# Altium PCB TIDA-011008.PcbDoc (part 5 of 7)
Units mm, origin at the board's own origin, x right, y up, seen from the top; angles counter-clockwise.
Board outline 252 x 205 mm, 4 copper layers (Top Layer, Inner Layer 1, Inner Layer 2, Bottom Layer), stack 1.926 mm thick; 517 components, 293 nets, 1426 pads, 1855 vias.
Unrouted connection lines stored in the file: 4.
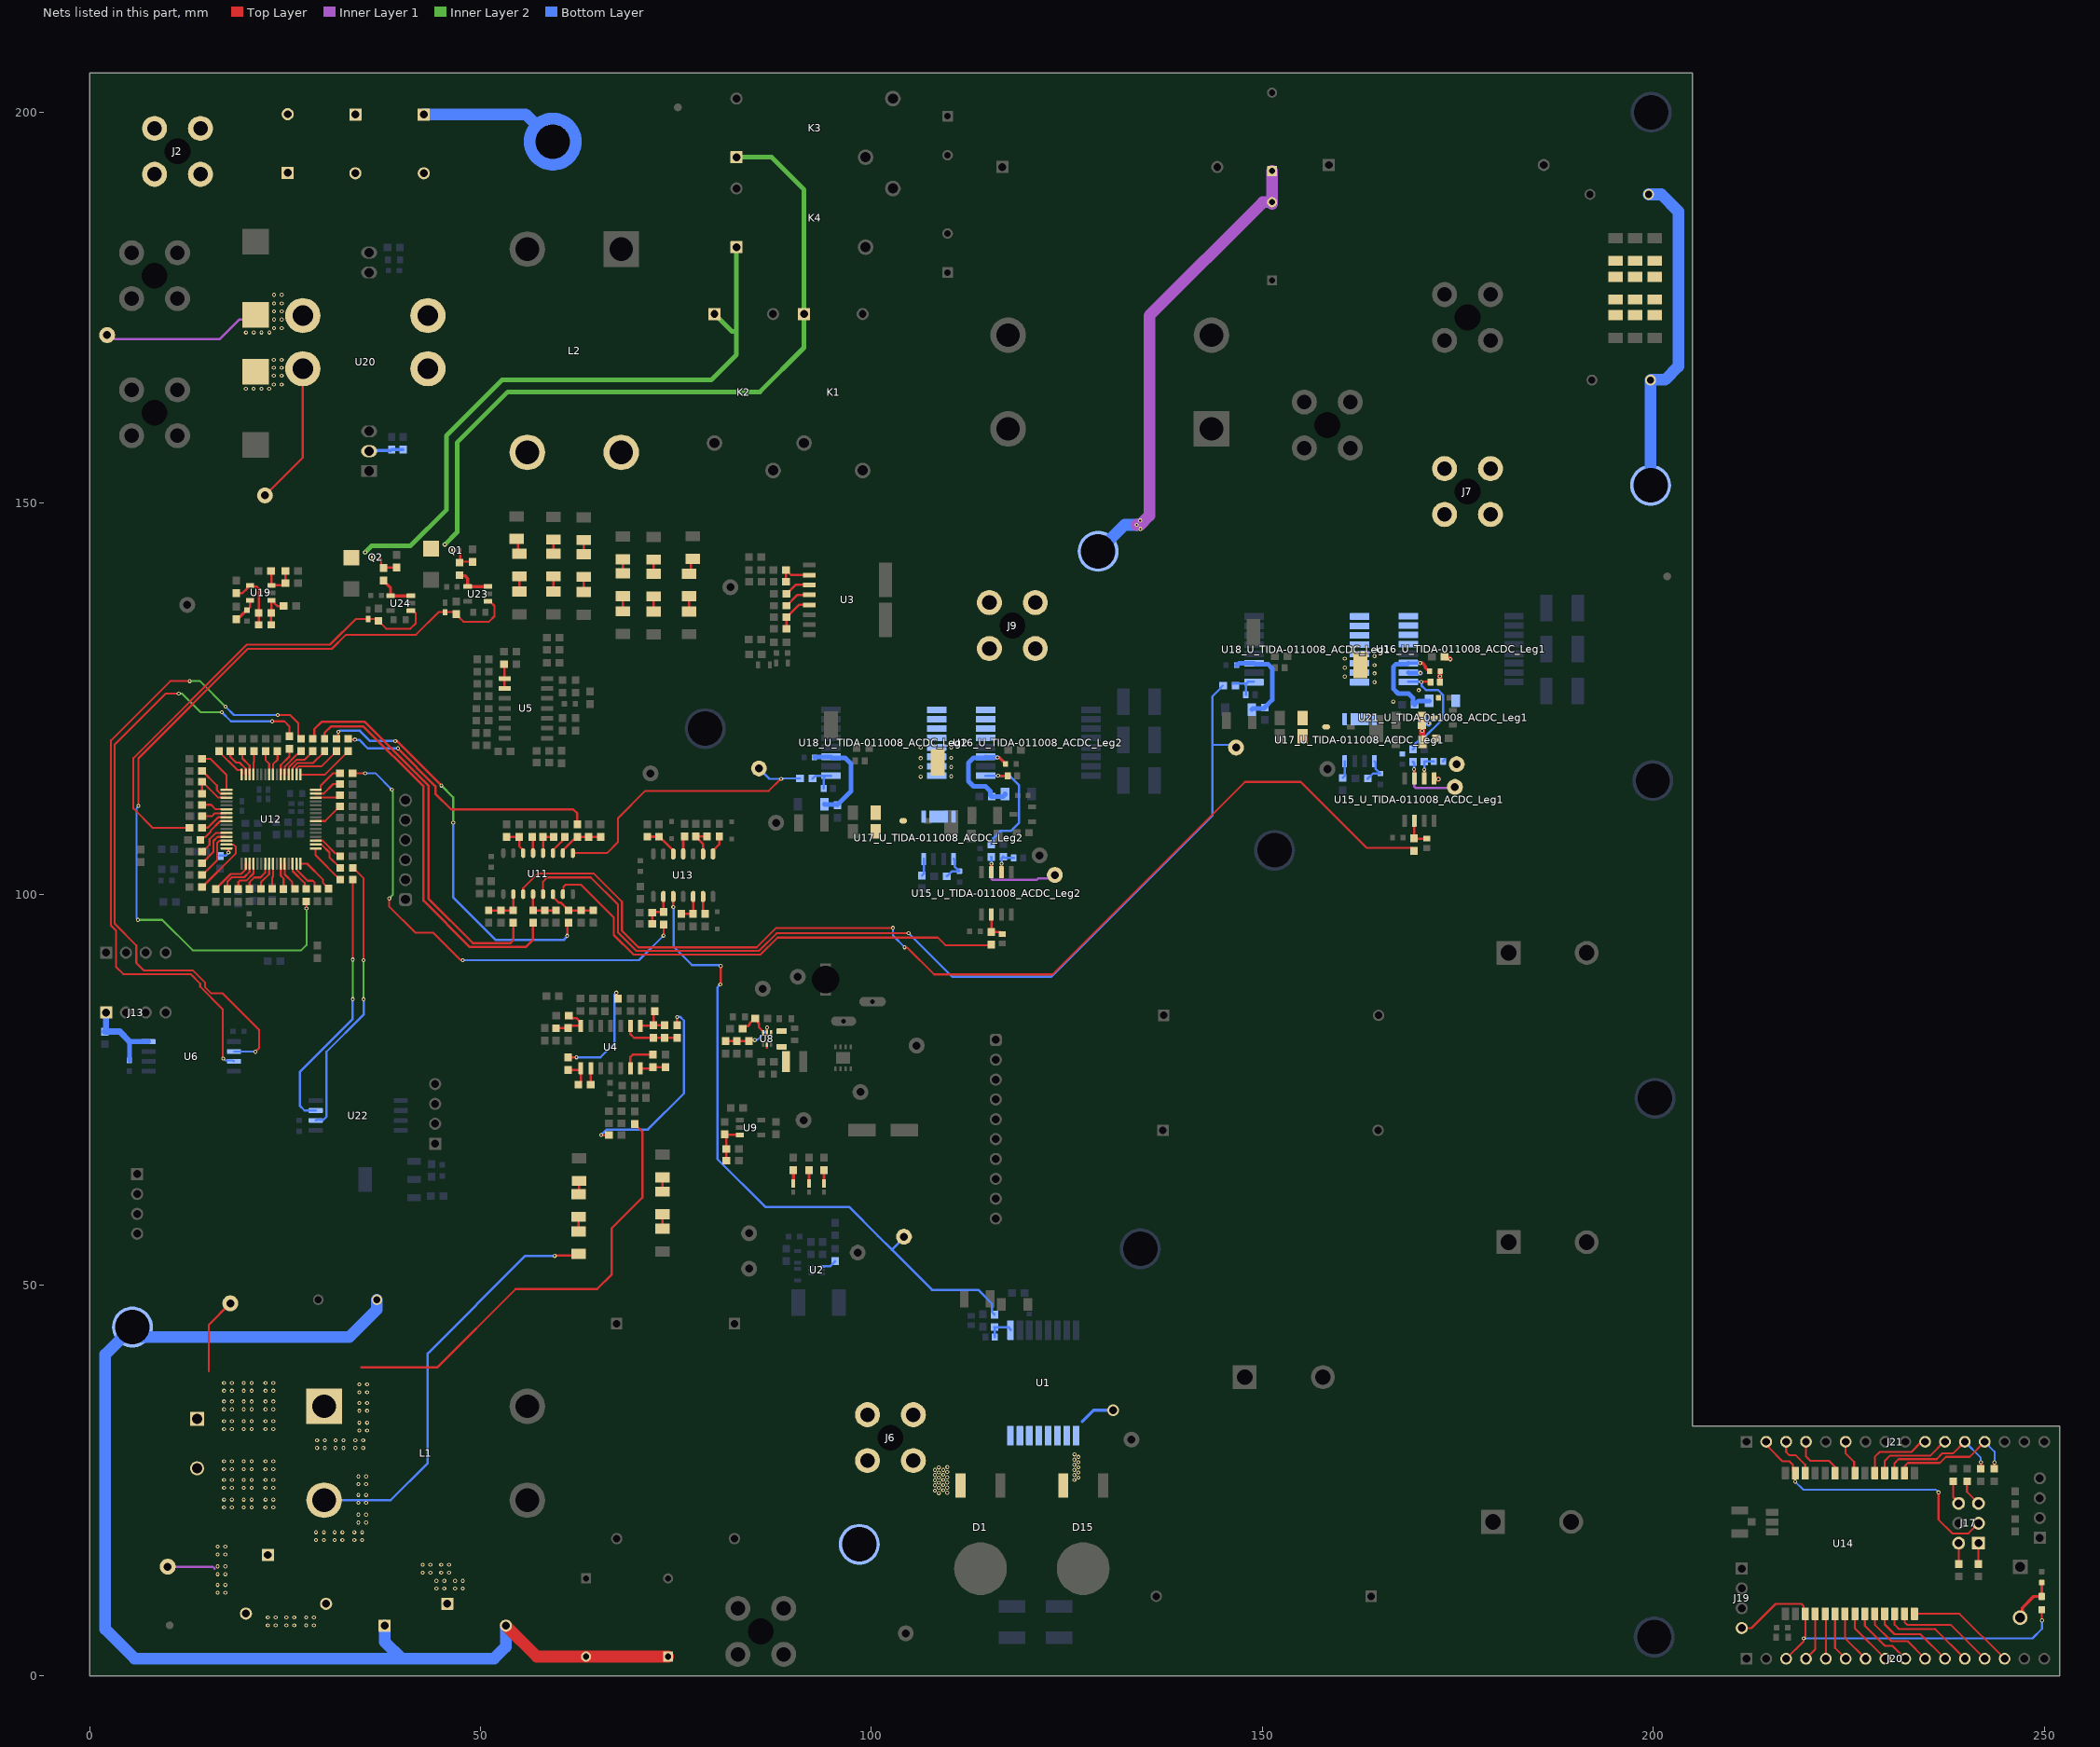
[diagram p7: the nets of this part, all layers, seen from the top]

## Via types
v1: diameter 0.508, hole 0.254, Top Layer to Bottom Layer, tented both sides, 1852 vias
v2: diameter 1.5/1.5/1.5/1.5 (per signal layer), hole 1, Top Layer to Bottom Layer, 2 vias
v3: diameter 0.508, hole 0.254, Top Layer to Bottom Layer, 1 vias

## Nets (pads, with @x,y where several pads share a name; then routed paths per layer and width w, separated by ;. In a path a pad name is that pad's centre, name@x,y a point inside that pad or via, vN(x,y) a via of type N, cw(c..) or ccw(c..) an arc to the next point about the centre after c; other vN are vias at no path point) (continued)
NetC63_2: C63.2 R86.1 R90.1 U4.14 | length 5.7
  Top Layer w0.3: R90.1@59.678,82.861 59.685,82.867 C63.2@61.204,82.867 61.505,83.168 62.844,83.168 62.844,83.593 62.279,84.158 61.604,84.158 R86.1@61.279,84.483
NetC64_1: C64.1 R89.1 R91.2 U4.9 | length 7.2
  Top Layer w0.3: U4.9@69.194,83.168 69.194,82.082 69.645,81.631 C64.1@72.146,81.631 R89.1@75.154,81.631
NetC64_2: C64.2 R87.1 R91.1 U4.8 | length 5
  Top Layer w0.3: U4.8@70.464,83.168 72.083,83.168 C64.2@72.146,83.231 ; R87.1@72.318,85.04 72.146,84.868 C64.2@72.146,83.231 ; R91.1@73.574,83.231 C64.2@72.146,83.231
NetC66_2: C66.2 J13.1 L6.2 U6.8 | length 10.5
  Bottom Layer w0.6: C66.2@5.093,78.76 5.093,81.112 ; 5.136,81.155 U6.8@7.56,81.155
  Bottom Layer w0.8: L6.2@1.961,82.431 3.86,82.431 5.136,81.155 5.093,81.112 ; L6.2@2.11,82.904 J13.1@2.11,84.879
NetC70_1: C70.1 L5.1 U8.2 | length 0.7
  Top Layer w0.3: 86.658,80.404 U8.2@86.658,80.785 ; C70.1@88.233,80.484 C70.1@88.533,80.484
NetC70_2: C70.2 U8.4
NetC78_2: C78.2 R101.1 R104.2 U9.3 | length 5.3
  Top Layer w0.3: R101.1@81.259,69.272 R101.1@81.323,69.208 ; C78.2@81.458,65.908 R104.2@81.458,67.408 81.458,69.073 R101.1@81.323,69.208 ; U9.3@83.183,69.208 R101.1@81.323,69.208
NetC81_2: C81.2 R102.1 R106.2 U8.5 | length 6.9
  Top Layer w0.254: v1(86.655,82.941) 86.657,82.94 86.657,82.266 U8.5@86.658,82.265
  Top Layer w0.3: C81.2@81.383,81.215 81.386,81.219 R106.2@82.808,81.219 82.81,81.217 R102.1@84.358,81.217 84.489,81.349 v1(85.083,81.349)
  Bottom Layer w0.254: v1(85.083,81.349) 85.122,81.388 85.428,81.388 86.626,82.586 86.626,82.912 v1(86.655,82.941)
NetC82_1: C82.1 R115.2 U11.12 | length 3.4
  Top Layer w0.3: U11.12@58.003,105.26 R115.2@58.003,107.335 C82.1@59.368,107.335
NetC83_1: C83.1 R118.2 U11.14 | length 3.9
  Top Layer w0.3: C83.1@53.368,107.335 R118.2@54.963,107.335 54.963,106.135 55.463,105.635 U11.14@55.463,105.26
NetC85_1: C85.1 R108.2 R128.2 U11.2 | length 5.2
  Top Layer w0.3: R128.2@51.047,97.935 C85.1@52.643,97.935 54.193,97.935 U11.2@54.193,100.01
NetC86_1: C86.1 R109.2 R129.2 U11.4 | length 5
  Top Layer w0.3: U11.4@56.733,100.01 R109.2@56.733,97.935 R129.2@58.253,97.935 C86.1@59.682,97.935
NetC87_1: C87.1 R111.2 R130.2 U11.6 | length 6.2
  Top Layer w0.3: U11.6@59.273,100.01 59.273,99.66 59.985,98.948 60.28,98.948 61.268,97.96 R111.2@61.268,97.935 R130.2@62.868,97.935 C87.1@64.406,97.935
NetC88_1: C88.1 R113.2 R131.2 U11.10 | length 5.9
  Top Layer w0.3: U11.10@60.543,105.26 60.543,105.61 61.918,106.985 62.068,106.985 62.393,107.31 R113.2@62.393,107.335 R131.2@63.831,107.335 C88.1@65.368,107.335
NetC90_1: C90.1 R142.2 R144.2 U13.2 | length 4.9
  Top Layer w0.3: C90.1@71.982,96.206 R144.2@71.982,97.635 72.079,97.731 R142.2@73.432,97.731 73.392,97.771 U13.2@73.392,99.706
NetC91_1: C91.1 R150.2 U13.5 | length 3.7
  Top Layer w0.3: C91.1@75.669,97.481 R150.2@77.169,97.481 77.202,97.515 U13.5@77.202,99.706
NetC96_1: C96.1 R153.2 U13.12 | length 4.5
  Top Layer w0.3: C96.1@71.319,107.355 R153.2@72.83,107.355 72.83,107.33 73.155,107.005 73.239,107.005 74.662,105.581 U13.12@74.662,105.156
NetC101_1: C101.1 R159.2 U13.9 | length 4.1
  Top Layer w0.3: U13.9@78.472,105.156 78.472,106.403 77.519,107.356 C101.1@77.519,107.381 R159.2@78.979,107.381
NetC102_1: C102.1 R158.1 U12.3 | length 5.5
  Top Layer w0.254: R158.1@14.39,112.865 C102.1@14.39,114.365 14.738,114.017 14.824,114.017 16.489,112.352 U12.3@17.515,112.352
NetC107_2: C107.2 R164.1 SW1.2 | length 6.2
  Top Layer w0.4: SW1.2@246.94,7.47 247.225,7.755 247.225,8.745 248.67,10.19 R164.1@249.69,10.19 C107.2@249.69,11.96
NetC112_U_TIDA-011008_ACDC_Leg1_1: C112_U_TIDA-011008_ACDC_Leg1.1 C113_U_TIDA-011008_ACDC_Leg1.2 R173_U_TIDA-011008_ACDC_Leg1.2 U16_U_TIDA-011008_ACDC_Leg1.11 | length 14.2
  Top Layer w0.4: v1(170.195,129.562) 170.214,129.542 170.484,129.542 170.87,129.157 170.87,128.964 171.167,128.667 171.269,128.667 171.394,128.542 C113_U_TIDA-011008_ACDC_Leg1.2@171.394,128.517
  Bottom Layer w0.4: U16_U_TIDA-011008_ACDC_Leg1.11@168.691,129.558 170.191,129.558 v1(170.195,129.562)
  Bottom Layer w0.6: U16_U_TIDA-011008_ACDC_Leg1.11@168.691,129.558 U16_U_TIDA-011008_ACDC_Leg1.11@168.687,129.554 168.562,129.429 167.094,129.429 166.755,129.089 166.755,126.279 167.377,125.657 168.721,125.657 169.278,125.1 169.278,124.424 169.453,124.249 R173_U_TIDA-011008_ACDC_Leg1.2@169.478,124.249 169.503,124.249 169.972,124.719 C112_U_TIDA-011008_ACDC_Leg1.1@171.35,124.719
NetC112_U_TIDA-011008_ACDC_Leg2_1: C112_U_TIDA-011008_ACDC_Leg2.1 C113_U_TIDA-011008_ACDC_Leg2.2 R173_U_TIDA-011008_ACDC_Leg2.2 U16_U_TIDA-011008_ACDC_Leg2.11 | length 13.8
  Top Layer w0.4: v1(116.137,117.489) 116.156,117.469 116.385,117.469 117.18,116.675 C113_U_TIDA-011008_ACDC_Leg2.2@117.18,116.65
  Bottom Layer w0.6: v1(116.137,117.489) 114.692,117.489 U16_U_TIDA-011008_ACDC_Leg2.11@114.605,117.576 114.48,117.451 113.08,117.451 112.422,116.793 112.422,114.447 113.072,113.797 114.591,113.797 115.199,113.189 115.199,112.667 115.374,112.492 R173_U_TIDA-011008_ACDC_Leg2.2@115.399,112.492 116.843,112.492 117.093,112.742 C112_U_TIDA-011008_ACDC_Leg2.1@117.093,112.827
NetC114_U_TIDA-011008_ACDC_Leg1_2: C114_U_TIDA-011008_ACDC_Leg1.2 R176_U_TIDA-011008_ACDC_Leg1.1 U15_U_TIDA-011008_ACDC_Leg1.6 | length 3.4
  Top Layer w0.3: U15_U_TIDA-011008_ACDC_Leg1.6@170.722,114.804 v1(170.722,115.921)
  Bottom Layer w0.3: v1(170.722,115.921) R176_U_TIDA-011008_ACDC_Leg1.1@170.722,116.95 170.764,116.992 C114_U_TIDA-011008_ACDC_Leg1.2@171.944,116.992
NetC114_U_TIDA-011008_ACDC_Leg2_2: C114_U_TIDA-011008_ACDC_Leg2.2 R176_U_TIDA-011008_ACDC_Leg2.1 U15_U_TIDA-011008_ACDC_Leg2.6 | length 3.5
  Top Layer w0.3: U15_U_TIDA-011008_ACDC_Leg2.6@116.627,102.808 116.627,103.876 v1(116.656,103.904)
  Inner Layer 1 w0.3: v1(116.656,103.904) v1@116.71,103.904
  Bottom Layer w0.3: v1(116.656,103.904) 116.656,104.591 R176_U_TIDA-011008_ACDC_Leg2.1@116.861,104.796 116.988,104.668 C114_U_TIDA-011008_ACDC_Leg2.2@118.204,104.668
NetC116_U_TIDA-011008_ACDC_Leg1_1: C116_U_TIDA-011008_ACDC_Leg1.1 R174_U_TIDA-011008_ACDC_Leg1.2 U15_U_TIDA-011008_ACDC_Leg1.2 | length 3.9
  Top Layer w0.3: U15_U_TIDA-011008_ACDC_Leg1.2@169.452,109.404 169.452,107.194 R174_U_TIDA-011008_ACDC_Leg1.2@169.412,107.154 169.459,107.107 C116_U_TIDA-011008_ACDC_Leg1.1@171.03,107.107
NetC116_U_TIDA-011008_ACDC_Leg2_1: C116_U_TIDA-011008_ACDC_Leg2.1 R174_U_TIDA-011008_ACDC_Leg2.2 U15_U_TIDA-011008_ACDC_Leg2.2 | length 3.9
  Top Layer w0.3: U15_U_TIDA-011008_ACDC_Leg2.2@115.357,97.408 115.357,95.198 R174_U_TIDA-011008_ACDC_Leg2.2@115.317,95.158 116.492,95.158 C116_U_TIDA-011008_ACDC_Leg2.1@116.742,94.908 C116_U_TIDA-011008_ACDC_Leg2.1@116.742,94.833
NetC118_U_TIDA-011008_ACDC_Leg1_1: C118_U_TIDA-011008_ACDC_Leg1.1 FB7_U_TIDA-011008_ACDC_Leg1.2 U17_U_TIDA-011008_ACDC_Leg1.1 | length 3.7
  Bottom Layer w0.3: C118_U_TIDA-011008_ACDC_Leg1.1@163.499,114.795 163.524,114.795 164.165,115.436 FB7_U_TIDA-011008_ACDC_Leg1.2@165.104,115.436 164.479,116.06 164.479,116.878 U17_U_TIDA-011008_ACDC_Leg1.1@164.354,117.004
NetC118_U_TIDA-011008_ACDC_Leg2_1: C118_U_TIDA-011008_ACDC_Leg2.1 FB7_U_TIDA-011008_ACDC_Leg2.2 U17_U_TIDA-011008_ACDC_Leg2.1 | length 3.7
  Bottom Layer w0.3: C118_U_TIDA-011008_ACDC_Leg2.1@109.655,102.299 109.68,102.299 110.321,102.94 FB7_U_TIDA-011008_ACDC_Leg2.2@111.26,102.94 110.636,103.565 110.636,104.382 U17_U_TIDA-011008_ACDC_Leg2.1@110.51,104.508
NetC124_U_TIDA-011008_ACDC_Leg1_1: C124_U_TIDA-011008_ACDC_Leg1.1 C125_U_TIDA-011008_ACDC_Leg1.2 R179_U_TIDA-011008_ACDC_Leg1.2 U18_U_TIDA-011008_ACDC_Leg1.11 | length 12.1
  Bottom Layer w0.6: C125_U_TIDA-011008_ACDC_Leg1.2@146.713,129.279 146.713,129.304 146.738,129.329 146.838,129.329 147.026,129.517 U18_U_TIDA-011008_ACDC_Leg1.11@148.938,129.517 ; C124_U_TIDA-011008_ACDC_Leg1.1@148.674,123.623 148.799,123.748 150.192,123.748 R179_U_TIDA-011008_ACDC_Leg1.2@150.317,123.873 150.317,123.898 151.262,124.843 151.262,128.882 150.716,129.429 149.062,129.429 U18_U_TIDA-011008_ACDC_Leg1.11@148.937,129.554
NetC124_U_TIDA-011008_ACDC_Leg2_1: C124_U_TIDA-011008_ACDC_Leg2.1 C125_U_TIDA-011008_ACDC_Leg2.2 R179_U_TIDA-011008_ACDC_Leg2.2 U18_U_TIDA-011008_ACDC_Leg2.11 | length 12.8
  Bottom Layer w0.6: C125_U_TIDA-011008_ACDC_Leg2.2@92.728,117.486 92.728,117.497 92.753,117.522 94.806,117.522 94.842,117.558 94.967,117.433 96.642,117.433 97.399,116.677 97.399,113.166 95.648,111.415 R179_U_TIDA-011008_ACDC_Leg2.2@95.648,111.39 95.59,111.448 94.049,111.448 C124_U_TIDA-011008_ACDC_Leg2.1@93.992,111.505
NetC128_2: C128.2 U12.16 | length 2.1
  Top Layer w0.3: U12.16@17.515,105.852 17.771,105.852 v1(17.771,105.327)
  Bottom Layer w0.3: C128.2@16.665,104.942 17.439,104.942 17.771,105.274 v1(17.771,105.327) v1@17.771,105.381
NetC130_1: C130.1 FB8.2 U19.5 | length 3.3
  Top Layer w0.3: FB8.2@20.132,136.323 20.525,136.716 U19.5@20.525,137.594
  Top Layer w0.4: C130.1@18.747,135.15 18.747,135.175 19.022,135.45 19.224,135.45 19.947,136.173 19.982,136.173 FB8.2@20.132,136.323
NetC131_1: C131.1 R196.1 R197.2 U19.3 | length 5.3
  Top Layer w0.3: R196.1@23.2,141.35 23.275,141.275 U19.3@23.275,139.494 24.753,139.494 R197.2@25.065,139.807 C131.1@25.065,141.307
NetC133_1: C133.1 R195.1 R198.1 U19.1 | length 5.1
  Top Layer w0.3: C133.1@23.235,134.448 R198.1@23.235,135.963 23.275,136.003 U19.1@23.275,137.594 23.475,137.594 23.625,137.444 23.625,137.244 24.015,136.855 R195.1@24.808,136.855
NetC133_2: C133.2 R194.1 R198.2 U19.4 | length 8.2
  Top Layer w0.3: R194.1@18.747,138.5 19.531,138.5 20.175,139.144 20.175,139.344 20.325,139.494 U19.4@20.525,139.494 20.675,139.344 21.36,139.344 21.635,139.069 R198.2@21.635,135.963 C133.2@21.635,134.448
NetC134_1: C134.1 R201.2 U20.2 | length 4.4
  Bottom Layer w0.4: U20.2@35.762,156.66 35.859,156.757 38.551,156.757 C134.1@38.648,156.854 38.649,156.855 R201.2@40.104,156.856 R201.2@40.104,156.856
NetD1_3: D1.3 D15.3 J6.1 U1.1 U1.2 U1.3 U1.4 U1.5 U1.6 U1.7 U1.8 | length 4.5
  Bottom Layer w0.4: 127,32.59 128.423,34.013 v2(130.938,34.013)
  other v1: 108.628,23.41 109.7,23.452 108.114,23.736 109.18,23.775 108.635,24.08 109.7,24.114 108.114,24.411 109.18,24.436 108.635,24.739 109.7,24.766 108.114,25.071 125.965,25.08 109.18,25.088 108.635,25.391 126.486,25.391 109.7,25.425 125.965,25.713 108.114,25.723 109.18,25.747 126.486,26.043 108.635,26.053 109.7,26.101 108.114,26.375 125.965,26.374 109.197,26.381 108.635,26.685 126.486,26.695 109.717,26.734 125.965,27.026 126.486,27.354 125.965,27.686 126.486,28.03 125.973,28.355
NetD6_1: D6.1 R98.1 | length 1.7
  Top Layer w0.4: D6.1@93.933,63.015 R98.1@93.933,64.695
NetD7_1: D7.1 R99.2 | length 1.7
  Top Layer w0.4: D7.1@92.033,63.015 R99.2@92.033,64.695
NetD8_1: D8.1 R100.2 | length 1.7
  Top Layer w0.4: D8.1@90.012,63.015 R100.2@90.012,64.695
NetD13_U_TIDA-011008_ACDC_Leg1_2: D13_U_TIDA-011008_ACDC_Leg1.2 R171_U_TIDA-011008_ACDC_Leg1.2 R172_U_TIDA-011008_ACDC_Leg1.2
NetD13_U_TIDA-011008_ACDC_Leg2_2: D13_U_TIDA-011008_ACDC_Leg2.2 R171_U_TIDA-011008_ACDC_Leg2.2 R172_U_TIDA-011008_ACDC_Leg2.2
NetF1_1: F1.1 TP11.1 U20.8 | length 20.2
  Inner Layer 1 w0.3: TP11.1@2.25,171.5 2.719,171.5 3.212,171.007 16.674,171.007 19.167,173.5 21.25,173.5
  other v1: 20.005,171.837 21,171.837 22,171.837 22.995,171.837 23.591,172.392 24.586,172.392 23.591,173.5 24.586,173.5 23.591,174.536 24.586,174.536 23.591,175.536 24.586,175.536 23.591,176.644 24.586,176.644
NetF2_1: F2.1 TP12.1 U20.9 | length 19.2
  Top Layer w0.3: TP12.1@22.435,151 27.282,155.847 U20.9@27.282,167.2
  Top Layer w1: U20.9@27.282,167.2 U20.9@28.229,167.2
  other v1: 19.986,164.634 20.981,164.634 21.981,164.634 22.977,164.634 23.572,165.189 24.567,165.189 23.572,166.297 24.567,166.297 23.572,167.333 24.567,167.333 23.572,168.333 24.567,168.333
NetJ17_1: J17.1 R162.1 | length 2.7
  Top Layer w0.254: R162.1@241.605,14.35 J17.1@241.605,17.01
NetJ17_2: J17.2 R163.1 | length 2.7
  Top Layer w0.254: J17.2@239.065,17.01 239.065,14.37 R163.1@239.085,14.35
NetJ17_5: J17.5 R165.2 | length 3.7
  Top Layer w0.254: R165.2@240.135,25.168 R165.2@240.135,24.918 240.135,23.56 J17.5@241.605,22.09
NetJ17_6: J17.6 R166.2 | length 3.1
  Top Layer w0.254: R166.2@238.36,24.918 238.36,22.88 239.065,22.175 J17.6@239.065,22.09
NetL2_3: L2.3 R13.1 R17.2 U20.6
NetL2_4: L2.4 R17.1 R24.2 U20.7
NetQ1_1: Q1.1@47.398,143.989 R27.2 R92.2 | length 2.9
  Top Layer w0.254: Q1.1@47.4,143.871 47.403,143.868 47.403,142.501 47.411,142.51 R92.2@48.964,142.51
NetQ2_1: Q2.1@37.114,143.095 R34.2 R93.2 | length 3.2
  Top Layer w0.254: Q2.1@37.116,142.977 37.169,142.977 37.32,142.826 R34.2@37.32,141.991
  Top Layer w0.3: R34.2@37.32,141.991 R34.2@37.607,141.704 37.675,141.772 R93.2@39.3,141.772
NetR8_1: R8.1 U2.1 | length 1.9
  Bottom Layer w0.3: U2.1@93.74,52.442 94.75,52.442 95.35,53.042 R8.1@95.35,53.067
NetR14_1: R14.1 R15.1 R16.1 R18.2 R19.2 R20.2
NetR18_1: R18.1 R19.1 R20.1 R21.2 R22.2 R23.2
NetR26_1: R26.1 U3.6 | length 3.5
  Top Layer w0.3: R26.1@89.121,136.89 89.146,136.89 90.531,138.276 U3.6@92.053,138.276
NetR27_1: R27.1 U23.3 U23.4 | length 4.9
  Top Layer w0.4: R27.1@47.302,140.801 47.366,140.737 47.993,140.737 48.365,140.366 U23.4@48.365,139.343 U23.3@50.965,139.343
NetR29_1: R29.1 R33.1 U3.4 | length 4.7
  Top Layer w0.3: R33.1@89.095,139.98 89.077,139.999 R29.1@89.077,141.446 89.102,141.446 89.732,140.816 U3.4@92.053,140.816
NetR30_1: R30.1 R32.1 U3.7 | length 5
  Top Layer w0.3: R30.1@89.121,133.959 R32.1@89.121,135.415 89.146,135.415 90.736,137.006 U3.7@92.053,137.006
NetR31_2: R31.2 U3.5 | length 3.4
  Top Layer w0.3: R31.2@89.127,138.39 89.152,138.39 90.308,139.546 U3.5@92.053,139.546
NetR34_1: R34.1 U24.3 U24.4 | length 4.9
  Top Layer w0.4: R34.1@37.607,140.104 37.607,140.079 38.501,139.185 U24.4@38.501,138.152 U24.3@41.101,138.152
NetR39_1: R39.1 R41.1 U4.1 | length 3.7
  Top Layer w0.3: R41.1@61.204,77.543 U4.1@62.706,77.543 ; R39.1@62.519,75.652 62.844,75.977 U4.1@62.844,77.718
NetR39_2: R39.2 U4.2 | length 2.1
  Top Layer w0.3: U4.2@64.114,77.718 64.114,75.657 R39.2@64.119,75.652
NetR40_1: R40.1 R42.1 U4.7 | length 3.3
  Top Layer w0.3: U4.7@70.464,77.718 71.914,77.718 R40.1@72.064,77.868 R42.1@73.654,77.868
NetR40_2: R40.2 U4.6 | length 4.5
  Top Layer w0.3: U4.6@69.194,77.718 69.194,79.19 69.472,79.468 R40.2@72.064,79.468
NetR43_2: R43.2 R44.1 | length 1.6
  Top Layer w0.3: R43.2@62.574,57.032 R44.1@62.574,58.589
NetR44_2: R44.2 R45.1 | length 1.4
  Top Layer w0.3: R44.2@62.574,61.789 62.597,61.812 62.597,63.159 R45.1@62.619,63.182
NetR46_2: R46.2 R47.1 | length 1.5
  Top Layer w0.3: R46.2@73.256,57.362 R47.1@73.256,58.912
NetR47_2: R47.2 R48.1 | length 1.5
  Top Layer w0.3: R47.2@73.256,62.112 R48.1@73.256,63.632
NetR49_1: R49.1 U5.8 U5.9 | length 3.1
  Top Layer w0.3: R49.1@52.993,129.397 53.101,129.289 53.101,127.574 U5.9@53.101,126.304
NetR58_2: R58.2 R59.1 | length 1.5
  Top Layer w0.3: R59.1@63.221,143.642 R58.2@63.221,145.15
NetR59_2: R59.2 R60.1 | length 1.6
  Top Layer w0.3: R60.1@63.221,138.802 R59.2@63.221,140.442
NetR61_2: R61.2 R62.1 | length 1.5
  Top Layer w0.3: R62.1@59.34,143.694 R61.2@59.34,145.203
NetR62_2: R62.2 R63.1 | length 1.6
  Top Layer w0.3: R63.1@59.34,138.854 R62.2@59.34,140.494
NetR64_2: R64.2 R65.1 | length 1.8
  Top Layer w0.3: R65.1@76.706,141.142 76.915,141.35 76.915,142.484 R64.2@77.153,142.722
NetR65_2: R65.2 R66.1 | length 1.6
  Top Layer w0.3: R66.1@76.706,136.302 R65.2@76.706,137.942
NetR70_2: R70.2 R71.1 | length 1.5
  Top Layer w0.3: R71.1@68.201,141.162 R70.2@68.201,142.671
NetR71_2: R71.2 R72.1 | length 1.6
  Top Layer w0.3: R72.1@68.201,136.323 R71.2@68.201,137.962
NetR73_2: R73.2 R74.1 | length 1.7
  Top Layer w0.3: R73.2@54.595,145.277 54.822,145.05 54.822,143.873 R74.1@54.995,143.7
NetR74_2: R74.2 R75.1 | length 1.6
  Top Layer w0.3: R75.1@54.995,138.86 R74.2@54.995,140.5
NetR76_2: R76.2 R77.1 | length 1.5
  Top Layer w0.3: R77.1@72.136,141.135 R76.2@72.136,142.643
NetR77_2: R77.2 R78.1 | length 1.6
  Top Layer w0.3: R78.1@72.136,136.295 R77.2@72.136,137.935
NetR103_1: R103.1 R105.2 U8.6 | length 4.5
  Top Layer w0.3: R105.2@83.533,82.808 83.858,83.133 84.225,83.133 84.401,83.309 84.401,83.432 85.1,84.132 R103.1@85.125,84.132 85.15,84.132 85.475,83.807 85.475,83.553 85.622,83.407 85.622,82.986 86.158,82.45 U8.6@86.158,82.265
NetR110_1: R110.1 U12.52 | length 4.9
  Top Layer w0.254: U12.52@25.465,115.302 25.488,115.325 25.488,116.231 26.469,117.211 27.523,117.211 28.563,118.252 R110.1@28.563,118.277
NetR112_1: R112.1 U12.51 | length 5.8
  Top Layer w0.254: U12.51@25.965,115.302 25.988,115.325 25.988,116.159 26.622,116.793 28.604,116.793 30.063,118.252 R112.1@30.063,118.277
NetR114_1: R114.1 U12.50 | length 6.8
  Top Layer w0.254: U12.50@26.465,115.302 26.488,115.325 26.488,116.088 26.741,116.341 29.652,116.341 31.563,118.252 R114.1@31.563,118.277
NetR116_1: R116.1 U11.11 | length 2.7
  Top Layer w0.3: U11.11@59.273,105.26 59.273,105.61 60.468,106.805 60.468,107.01 R116.1@60.793,107.335
NetR117_1: R117.1 U12.49 | length 7.3
  Top Layer w0.254: U12.49@26.965,115.302 30.114,115.302 33.063,118.252 R117.1@33.063,118.277
NetR119_1: R119.1 U11.13 | length 2.1
  Top Layer w0.3: R119.1@56.618,107.335 56.733,107.22 U11.13@56.733,105.26
NetR120_1: R120.1 U12.48 | length 4.3
  Top Layer w0.254: U12.48@28.915,113.352 29.515,113.352 29.538,113.375 29.538,113.848 31.165,115.475 R120.1@32.046,115.475
NetR121_1: R121.1 U12.61 | length 3
  Top Layer w0.254: U12.61@20.965,115.302 20.965,116.866 21.04,116.941 R121.1@21.04,118.277
NetR122_1: R122.1 U12.64 | length 4.5
  Top Layer w0.254: R122.1@16.54,118.277 16.54,118.252 18.917,115.876 19.442,115.876 19.465,115.853 U12.64@19.465,115.302
NetR123_1: R123.1 U12.57 | length 3.2
  Top Layer w0.254: R123.1@22.54,118.277 22.54,117.116 22.965,116.691 U12.57@22.965,115.302
NetR124_1: R124.1 U12.47 | length 3.6
  Top Layer w0.254: U12.47@28.915,112.852 28.938,112.875 29.941,112.875 31.165,114.1 R124.1@32.046,114.1
NetR125_1: R125.1 U12.62 | length 3.4
  Top Layer w0.254: R125.1@19.54,118.277 19.54,117.366 20.465,116.441 U12.62@20.465,115.302
NetR126_1: R126.1 U12.63 | length 4.1
  Top Layer w0.254: R126.1@18.015,118.277 18.015,117.543 18.718,116.841 19.19,116.841 19.942,116.088 19.942,115.325 U12.63@19.965,115.302
NetR127_1: R127.1 U12.56 | length 3.2
  Top Layer w0.254: U12.56@23.465,115.302 23.465,116.616 24.04,117.191 R127.1@24.04,118.277
NetR132_1: R132.1 U12.23 | length 4.5
  Top Layer w0.254: R132.1@20.463,100.666 20.463,101.524 21.082,102.143 21.869,102.143 22.442,102.717 22.442,103.879 U12.23@22.465,103.902
NetR133_1: R133.1 U12.14 | length 6.2
  Top Layer w0.254: R133.1@14.39,102.44 14.415,102.44 16.318,104.343 16.318,106.542 16.605,106.829 17.492,106.829 U12.14@17.515,106.852
NetR134_1: R134.1 U12.18 | length 5.6
  Top Layer w0.254: R134.1@16.154,100.656 16.154,100.681 18.054,102.581 19.406,102.581 19.942,103.116 19.942,103.879 U12.18@19.965,103.902
NetR135_1: R135.1 U12.13 | length 5.4
  Top Layer w0.254: R135.1@14.39,103.965 14.415,103.965 15.849,105.399 15.849,106.811 16.367,107.329 17.492,107.329 U12.13@17.515,107.352
NetR136_1: R136.1 U12.19 | length 5.3
  Top Layer w0.254: R136.1@17.628,100.656 17.628,101.584 18.221,102.177 19.785,102.177 20.465,102.857 U12.19@20.465,103.902
NetR138_1: R138.1 U12.20 | length 4.5
  Top Layer w0.254: R138.1@19.029,100.656 19.029,101.553 19.248,101.773 20.094,101.773 20.965,102.644 U12.20@20.965,103.902
NetR139_1: R139.1 U12.25 | length 3.3
  Top Layer w0.254: R139.1@23.348,100.672 23.348,102.115 23.465,102.232 U12.25@23.465,103.902
NetR140_1: R140.1 U12.12 | length 4.5
  Top Layer w0.254: R140.1@14.39,105.465 14.738,105.813 14.852,105.813 15.345,106.306 15.345,107.041 16.157,107.853 U12.12@17.515,107.852
NetR141_1: R141.1 U12.9 | length 4.2
  Top Layer w0.254: R141.1@14.39,107.029 14.39,107.145 14.552,107.307 14.826,107.307 15.468,107.949 15.468,108.108 16.689,109.329 17.492,109.329 U12.9@17.515,109.352
NetR143_1: R143.1 U12.27 | length 3.4
  Top Layer w0.254: U12.27@24.465,103.902 24.465,102.345 24.811,102 R143.1@24.811,100.67
NetR145_1: R145.1 U12.28 | length 3.8
  Top Layer w0.254: U12.28@24.965,103.902 24.965,102.531 25.937,101.559 25.937,101.021 R145.1@26.285,100.673
NetR146_1: R146.1 U12.30 | length 4
  Top Layer w0.254: U12.30@25.965,103.902 25.988,103.879 25.988,102.95 27.515,101.423 27.515,100.868 R146.1@27.71,100.673
NetR147_1: R147.1 U12.34 | length 4.7
  Top Layer w0.254: U12.34@28.915,106.352 28.938,106.329 29.701,106.329 30.696,105.334 30.696,104.717 32.039,103.374 R147.1@32.064,103.374
NetR148_1: R148.1 U12.7 | length 3.3
  Top Layer w0.254: R148.1@14.39,109.965 15.646,109.965 16.033,110.352 U12.7@17.515,110.352
NetR149_1: R149.1 U12.8 | length 3.7
  Top Layer w0.254: R149.1@14.39,108.49 14.412,108.512 15.123,108.512 16.44,109.829 17.492,109.829 U12.8@17.515,109.852
NetR151_1: R151.1 U13.6 | length 2.3
  Top Layer w0.3: U13.6@78.472,99.706 78.472,97.728 R151.1@78.719,97.481
NetR152_1: R152.1 U12.33 | length 5.3
  Top Layer w0.254: U12.33@28.915,105.852 28.915,104.979 32.039,101.856 R152.1@32.064,101.856
NetR154_1: R154.1 U13.11 | length 2.3
  Top Layer w0.3: U13.11@75.932,105.156 75.932,107.208 R154.1@76.105,107.381
NetR160_1: R160.1 U13.8 | length 2.6
  Top Layer w0.3: U13.8@79.742,105.156 79.742,105.581 80.554,106.393 R160.1@80.554,107.381
NetR161_1: R161.1 U12.46 | length 3.3
  Top Layer w0.254: U12.46@28.915,112.352 31.749,112.352 R161.1@32.046,112.65
NetR175_U_TIDA-011008_ACDC_Leg1_1: R175_U_TIDA-011008_ACDC_Leg1.1 TP26_U_TIDA-011008_ACDC_Leg1.1 U15_U_TIDA-011008_ACDC_Leg1.7 | length 9.7
  Top Layer w0.3: v1(169.412,115.962) 169.452,115.921 U15_U_TIDA-011008_ACDC_Leg1.7@169.452,114.804
  Inner Layer 1 w0.3: v1(169.412,115.962) 169.412,113.78 169.588,113.604 174.457,113.604 TP26_U_TIDA-011008_ACDC_Leg1.1@174.617,113.443
  Bottom Layer w0.3: R175_U_TIDA-011008_ACDC_Leg1.1@169.267,116.937 169.412,116.793 v1(169.412,115.962)
NetR175_U_TIDA-011008_ACDC_Leg2_1: R175_U_TIDA-011008_ACDC_Leg2.1 TP26_U_TIDA-011008_ACDC_Leg2.1 U15_U_TIDA-011008_ACDC_Leg2.7 | length 12
  Top Layer w0.3: U15_U_TIDA-011008_ACDC_Leg2.7@115.357,102.809 v1(115.356,103.897)
  Inner Layer 1 w0.3: v1@115.374,103.915 v1(115.356,103.897) 115.356,102 115.532,101.824 121.149,101.824 121.354,102.029 122.821,102.029 TP26_U_TIDA-011008_ACDC_Leg2.1@123.138,102.346
  Bottom Layer w0.3: R175_U_TIDA-011008_ACDC_Leg2.1@115.323,104.771 115.356,104.738 v1(115.356,103.897)
NetR178_U_TIDA-011008_ACDC_Leg1_2: R178_U_TIDA-011008_ACDC_Leg1.2 U17_U_TIDA-011008_ACDC_Leg1.4 | length 2.2
  Bottom Layer w0.3: R178_U_TIDA-011008_ACDC_Leg1.2@160.298,114.87 160.544,115.115 U17_U_TIDA-011008_ACDC_Leg1.4@160.544,117.004
NetR178_U_TIDA-011008_ACDC_Leg2_2: R178_U_TIDA-011008_ACDC_Leg2.2 U17_U_TIDA-011008_ACDC_Leg2.4 | length 2.2
  Bottom Layer w0.3: R178_U_TIDA-011008_ACDC_Leg2.2@106.455,102.374 106.7,102.619 U17_U_TIDA-011008_ACDC_Leg2.4@106.7,104.508
NetR182_1: R182.1 U12.1 | length 5.9
  Top Layer w0.254: R182.1@14.39,117.319 15.446,117.319 17.515,115.249 U12.1@17.515,113.352
NetR183_1: R183.1 U12.40 | length 3.9
  Top Layer w0.254: U12.40@28.915,109.352 30.124,109.352 32.021,111.25 R183.1@32.046,111.25
NetR184_1: R184.1 U12.53 | length 3.9
  Top Layer w0.254: U12.53@24.965,115.302 24.988,115.325 24.988,116.346 26.547,117.904 26.692,117.904 27.04,118.252 R184.1@27.04,118.277
NetR185_1: R185.1 U12.2 | length 4.7
  Top Layer w0.254: R185.1@14.39,115.769 14.415,115.769 16.287,113.897 16.287,113.318 16.73,112.875 17.492,112.875 U12.2@17.515,112.852
NetR186_1: R186.1 U12.24 | length 3.7
  Top Layer w0.254: R186.1@21.908,100.684 21.908,101.506 22.965,102.563 U12.24@22.965,103.902
NetR187_1: R187.1 U12.54 | length 3.8
  Top Layer w0.254: U12.54@24.465,115.302 24.465,116.519 25.56,117.614 R187.1@25.56,118.604
NetR188_1: R188.1 U12.15 | length 8.2
  Top Layer w0.254: R188.1@14.39,100.915 14.415,100.915 18.693,105.193 18.693,106.067 18.431,106.329 17.538,106.329 U12.15@17.515,106.352
NetR189_1: R189.1 U12.35 | length 4
  Top Layer w0.254: U12.35@28.915,106.852 28.924,106.843 29.808,106.843 31.448,105.204 31.708,105.204 R189.1@32.056,104.856
NetR199_1: R199.1 U12.6 | length 3.4
  Top Layer w0.254: R199.1@14.393,111.434 15.55,111.434 16.131,110.852 U12.6@17.515,110.852
NetR200_1: R200.1 U12.31 | length 4.7
  Top Layer w0.254: U12.31@26.465,103.902 26.488,103.879 26.488,103.116 27.889,101.715 28.563,101.715 28.797,101.482 28.797,101.029 R200.1@29.145,100.681
NetR202_1: R202.1 U12.32 | length 5.2
  Top Layer w0.254: U12.32@26.965,103.902 27.823,103.902 29.87,101.856 29.87,101.445 30.593,100.722 R202.1@30.593,100.697
P12_GPIO32: J20.4 U14.4 | length 6.2
  Top Layer w0.254: J20.4@219.54,2.225 220.72,3.405 U14.4@220.72,7.975
P13_GPIO31: J20.5 U14.5 | length 5.8
  Top Layer w0.254: U14.5@221.99,7.975 222.08,7.885 J20.5@222.08,2.225
P14_GPIO30: J20.6 U14.6 | length 6.3
  Top Layer w0.254: U14.6@223.26,7.975 223.26,3.585 J20.6@224.62,2.225
P16_GPIO29: J20.7 U14.7 | length 6.8
  Top Layer w0.254: U14.7@224.53,7.975 224.53,4.855 J20.7@227.16,2.225
P17_GPIO28: J20.8 U14.8 | length 7.4
  Top Layer w0.254: U14.8@225.8,7.975 225.8,6.125 J20.8@229.7,2.225
P18_GPIO27: J20.9 U14.9 | length 8.4
  Top Layer w0.254: U14.9@227.07,7.975 227.07,6.445 229.645,3.87 230.595,3.87 J20.9@232.24,2.225
P19_GPIO26: J20.10 U14.10 | length 9.6
  Top Layer w0.254: U14.10@228.34,7.975 228.34,6.585 230.465,4.46 232.545,4.46 J20.10@234.78,2.225
P29_GPIO17: J20.11 U14.11 | length 10.9
  Top Layer w0.254: U14.11@229.61,7.975 229.61,6.618 230.869,5.36 234.185,5.36 J20.11@237.32,2.225
P30_GPIO16: J20.12 U14.12 | length 12.2
  Top Layer w0.254: U14.12@230.88,7.975 230.88,6.577 231.457,6 236.085,6 J20.12@239.86,2.225
P31_GPIO15: J20.13 U14.13 | length 13.3
  Top Layer w0.254: U14.13@232.15,7.975 232.15,6.9 232.477,6.573 238.052,6.573 J20.13@242.4,2.225
P32_GPIO14: J20.14 U14.14 | length 13.9
  Top Layer w0.254: U14.14@233.42,7.975 239.19,7.975 J20.14@244.94,2.225
P33_GPIO13: J21.11 U14.18 | length 10.3
  Top Layer w0.254: U14.18@229.61,25.975 229.61,27.52 230.299,28.209 235.459,28.209 237.226,29.975 J21.11@237.32,29.975
P34_GPIO12: J21.10 U14.19 | length 9.3
  Top Layer w0.254: U14.19@228.34,25.975 228.34,28.04 228.975,28.675 233.019,28.675 234.08,29.737 234.542,29.737 J21.10@234.78,29.975
P35_GPIO11: J21.13 R170.1 U14.16 | length 16.4
  Top Layer w0.254: U14.16@232.15,25.975 232.183,26.008 232.183,26.875 232.575,27.267 236.655,27.267 237.441,28.052 240.477,28.052 J21.13@242.4,29.975 ; R170.1@243.615,26.518 243.649,26.552 v1(243.649,27.327)
  Bottom Layer w0.254: J21.13@242.4,29.975 243.661,28.714 243.661,27.339 v1(243.649,27.327)
P36_GPIO10: J21.12 R169.1 U14.17 | length 15.7
  Top Layer w0.254: U14.17@230.88,25.975 230.88,27.249 231.381,27.75 236.247,27.75 237.001,28.504 238.389,28.504 J21.12@239.86,29.975 ; R169.1@241.865,26.518 241.918,26.571 v1(241.918,27.365)
  Bottom Layer w0.254: J21.12@239.86,29.975 241.871,27.964 241.871,27.412 v1(241.918,27.365)
P43_GPIO4: J21.4 U14.23 | length 7
  Top Layer w0.254: J21.4@219.61,29.975 J21.4@219.54,29.975 219.54,28.103 220.106,27.536 222.489,27.536 223.26,26.765 U14.23@223.26,25.975
P44_GPIO3: J21.6 U14.21 | length 4.5
  Top Layer w0.254: J21.6@224.62,29.975 224.62,28.48 225.702,27.398 225.702,26.073 U14.21@225.8,25.975
  Bottom Layer w0.254: J21.6@224.608,29.963 J21.6@224.62,29.975
P52_GPIO37: J17.3 J21.2 U14.27 | length 35.9
  Top Layer w0.254: J21.2@214.46,29.975 214.46,29.638 214.793,29.305 214.793,29.217 216.533,27.477 217.41,27.477 217.857,27.03 217.857,26.298 U14.27@218.18,25.975 218.15,25.945 v1(218.15,24.881) ; v1(236.495,23.503) 236.495,20.015 238.252,18.258 240.313,18.258 J17.3@241.605,19.55
  Bottom Layer w0.254: v1(218.15,24.881) 219.17,23.86 236.138,23.86 v1(236.495,23.503)
P53_GPIO36: J21.3 U14.26 | length 5.5
  Top Layer w0.254: J21.3@217,29.975 217,28.678 217.436,28.242 218.239,28.242 219.45,27.032 U14.26@219.45,25.975
PE: J2.1 R13.2 R24.1 | length 18
  Bottom Layer w1.5: R24.1@42.75,199.702 42.775,199.727 55.773,199.727 59.25,196.25
PE1: C7.1 C8.1 C20.2 MP1.1 R2.1 R6.2 | length 158.2
  Top Layer w1.5: R6.2@53.25,6.45 57.2,2.5 C20.2@63.5,2.5 C8.1@74,2.5
  Bottom Layer w1.5: C7.1@36.75,48.138 36.75,46.893 33.202,43.345 6.789,43.345 MP1.1@5.489,44.645 2,41.156 2,6 5.75,2.25 39.9,2.25 ; R2.1@37.75,6.45 37.775,6.425 37.775,4.375 39.9,2.25 ; R6.2@53.25,6.45 53.24,6.44 53.24,3.75 51.74,2.25 39.9,2.25
PE2: MP2.1
PE3: C25.1 C31.2 MP3.1 | length 42.2
  Bottom Layer w1.5: C25.1@199.415,189.5 201.027,189.5 203.207,187.321 203.207,167.478 201.522,165.792 199.708,165.792 C31.2@199.665,165.75 MP3.1@199.665,152.295
PE4: C24.2 C30.1 MP4.1 | length 59.9
  Inner Layer 1 w1.5: v1(133.936,147.231) 134.38,147.231 135.548,148.4 135.548,173.98 150.068,188.5 C24.2@151.25,188.5 ; C24.2@151.25,188.294 C24.2@151.25,188.5 ; C30.1@151.25,192.5 C24.2@151.25,188.5
  Bottom Layer w1.5: MP4.1@129.01,143.85 132.391,147.231 v1(133.936,147.231)
  other v1: 134.417,146.715 134.38,147.787
PE5: MP5.1
PV_Input+: J3.2 L1.2 R2.2 R4.2 R43.1 TP1.1 | length 59.9
  Top Layer w0.3: v1(59.5,53.75) 59.538,53.788 62.53,53.788 R43.1@62.574,53.832
  Inner Layer 1 w0.3: TP1.1@10,14 15.75,14 16,13.75
  Bottom Layer w0.3: L1.2@30,22.5 38.5,22.5 43.25,27.25 43.25,41.25 55.75,53.75 v1(59.5,53.75)
  other v1: 22.8,6.505 23.8,6.505 25.175,6.505 26.175,6.505 27.7,6.505 28.7,6.505 22.8,7.5 23.8,7.5 25.175,7.5 26.175,7.5 27.7,7.5 28.7,7.5 16.375,10.66 17.37,10.66 16.375,11.66 17.37,11.66 16.375,13.035 17.37,13.035 16.375,14.035 17.37,14.035 16.375,15.56 17.37,15.56 16.375,16.56 17.37,16.56 28.968,17.406 29.968,17.406 31.343,17.406 32.343,17.406 33.868,17.406 34.868,17.406 28.968,18.402 29.968,18.402 31.343,18.402 32.343,18.402 33.868,18.402 34.868,18.402 34.373,19.646 35.368,19.646 34.373,20.646 35.368,20.646 17.2,21.568 18.195,21.568 19.734,21.568 20.729,21.568 22.505,21.568 23.5,21.568 34.373,22.171 35.368,22.171 17.2,22.568 18.195,22.568 19.734,22.568 20.729,22.568 22.505,22.568 23.5,22.568 34.373,23.171 35.368,23.171 17.2,24.093 18.195,24.093 19.734,24.093 20.729,24.093 22.505,24.093 23.5,24.093 34.373,24.546 35.368,24.546 17.2,25.093 18.195,25.093 19.734,25.093 20.729,25.093 22.505,25.093 23.5,25.093 34.373,25.546 35.368,25.546 17.2,26.468 18.195,26.468 19.734,26.468 20.729,26.468 22.505,26.468 23.5,26.468 17.2,27.468 18.195,27.468 19.734,27.468 20.729,27.468 22.505,27.468 23.5,27.468
PV_Input-: J3.1 L1.1 R4.1 R6.1 R53.1 TP6.1 | length 68
  Top Layer w0.254: 15.25,39 15.25,44.931 TP6.1@18,47.681
  Top Layer w0.3: 34.75,39.5 44.5,39.5 54.5,49.5 64.92,49.5 66.765,51.345 66.765,57.25 70.714,61.2 70.714,69.639 69.761,70.593 R53.1@69.761,70.618
  other v1: 44.375,11.2 45.375,11.2 46.75,11.2 47.75,11.2 44.375,12.195 45.375,12.195 46.75,12.195 47.75,12.195 42.6,13.244 43.6,13.244 44.975,13.244 45.975,13.244 42.6,14.24 43.6,14.24 44.975,14.24 45.975,14.24 29.1,29.171 30.1,29.171 31.475,29.171 32.475,29.171 34,29.171 35,29.171 29.1,30.167 30.1,30.167 31.475,30.167 32.475,30.167 34,30.167 35,30.167 34.505,31.411 35.5,31.411 17.2,31.6 18.195,31.6 19.734,31.6 20.729,31.6 22.505,31.6 23.5,31.6 34.505,32.411 35.5,32.411 17.2,32.6 18.195,32.6 19.734,32.6 20.729,32.6 22.505,32.6 23.5,32.6 34.505,33.936 35.5,33.936 17.2,34.125 18.195,34.125 19.734,34.125 20.729,34.125 22.505,34.125 23.5,34.125 34.505,34.936 35.5,34.936 17.2,35.125 18.195,35.125 19.734,35.125 20.729,35.125 22.505,35.125 23.5,35.125 34.505,36.311 35.5,36.311 17.2,36.5 18.195,36.5 19.734,36.5 20.729,36.5 22.505,36.5 23.5,36.5 34.505,37.311 35.5,37.311 17.2,37.5 18.195,37.5 19.734,37.5 20.729,37.5 22.505,37.5 23.5,37.5
PV_Input_buffer+: R41.2 R85.2 | length 14.1
  Top Layer w0.3: R41.2@61.204,79.143 v1(62.279,79.143) ; v1(67.379,87.407) 67.379,86.867 R85.2@67.589,86.657
  Bottom Layer w0.3: v1(62.279,79.143) 65.354,79.143 67.154,80.943 67.154,87.182 v1(67.379,87.407)
PV_Input_buffer-: R54.2 R89.2 | length 25.2
  Top Layer w0.3: v1(65.429,69.193) R54.2@66.424,69.193 ; R89.2@75.154,83.231 v1(75.154,84.29)
  Bottom Layer w0.3: v1(65.429,69.193) 66.154,69.918 71.421,69.918 76.026,74.523 76.026,83.836 75.571,84.29 v1(75.154,84.29)
PWM_1A: R174_U_TIDA-011008_ACDC_Leg1.1 U11.3 | length 139.5
  Top Layer w0.254: U11.3@55.463,100.01 55.463,100.786 57.312,102.635 64.51,102.635 68.09,99.055 68.09,95.314 70.212,93.191 85.329,93.191 87.827,95.689 v1(102.757,95.689) ; v1(104.261,93.213) 104.308,93.166 104.586,93.166 108.013,89.739 123.155,89.739 147.781,114.366 154.921,114.366 163.36,105.927 169.064,105.927 169.412,105.579 R174_U_TIDA-011008_ACDC_Leg1.1@169.412,105.554
  Bottom Layer w0.254: v1(102.757,95.689) 102.757,94.718 v1(104.261,93.213)
PWM_1A_mcu: R108.1 R110.2 | length 49.7
  Top Layer w0.3: R110.2@28.563,119.877 28.754,120.067 28.754,121.106 29.723,122.075 35.15,122.075 43.334,113.891 43.334,99.433 49.017,93.75 53.843,93.75 54.193,94.1 R108.1@54.193,96.335
PWM_1B: R180_U_TIDA-011008_ACDC_Leg1.1 TP30_U_TIDA-011008_ACDC_Leg1.1 U11.5 | length 125.5
  Top Layer w0.254: U11.5@58.003,100.01 58.003,101.606 58.533,102.135 64.118,102.135 67.589,98.664 67.589,95.123 69.962,92.75 85.622,92.75 87.872,95 104.741,95 v1(104.756,95.015)
  Bottom Layer w0.254: v1(104.756,95.015) 110.331,89.44 123.03,89.44 143.615,110.025 143.615,119.096 ; R180_U_TIDA-011008_ACDC_Leg1.1@144.977,126.662 144.952,126.662 144.604,126.314 144.604,126.289 143.615,125.3 143.615,119.096 ; TP30_U_TIDA-011008_ACDC_Leg1.1@146.643,118.758 146.305,119.096 143.615,119.096
PWM_1B_mcu: R109.1 R112.2 | length 50.6
  Top Layer w0.3: R112.2@30.063,119.877 30.063,120.627 30.915,121.479 34.999,121.479 42.706,113.772 42.706,99.167 48.623,93.25 55.806,93.25 56.733,94.177 R109.1@56.733,96.335
PWM_2A: R174_U_TIDA-011008_ACDC_Leg2.1 U11.7 | length 62.1
  Top Layer w0.254: U11.7@60.543,100.01 60.6,100.066 60.6,100.921 60.9,101.22 62.855,101.22 67.057,97.018 67.057,94.783 69.547,92.294 85.836,92.294 87.986,94.444 108.491,94.444 109.452,93.483 115.242,93.483 R174_U_TIDA-011008_ACDC_Leg2.1@115.317,93.558
PWM_2A_mcu: R111.1 R114.2 | length 50.9
  Top Layer w0.3: R114.2@31.563,119.877 31.812,120.125 v1(31.812,120.754) ; v1(39.112,119.578) 39.314,119.578 v1(45,113.892) ; v1(61.101,94.678) 61.101,96.167 R111.1@61.268,96.335
  Inner Layer 2 w0.3: v1(45,113.892) 46.513,112.379 v1(46.513,109.156)
  Bottom Layer w0.3: v1(31.812,120.754) 31.868,120.754 32.003,120.888 34.575,120.888 35.885,119.578 v1(39.112,119.578) ; v1@46.527,109.142 46.527,99.568 51.918,94.177 60.672,94.177 61.101,94.606 v1(61.101,94.678) v1@61.101,94.75
PWM_2B: R180_U_TIDA-011008_ACDC_Leg2.1 TP30_U_TIDA-011008_ACDC_Leg2.1 U11.9 | length 38.2
  Top Layer w0.254: U11.9@61.813,105.26 66.184,105.26 67.589,106.665 67.589,109.712 71.089,113.212 86.891,113.212 88.423,114.744 v1(88.47,114.744)
  Bottom Layer w0.254: TP30_U_TIDA-011008_ACDC_Leg2.1@85.618,116.081 86.956,114.744 v1(88.47,114.744) 88.514,114.788 90.863,114.788 R180_U_TIDA-011008_ACDC_Leg2.1@90.878,114.803
PWM_2B_mcu: R113.1 R117.2 | length 35.2
  Top Layer w0.3: R117.2@33.063,119.877 33.171,119.769 v1(33.931,119.769) ; v1(39.443,118.647) 39.443,118.61 44.242,113.812 44.242,112.86 46.259,110.843 61.861,110.843 62.393,110.311 R113.1@62.393,108.935
  Bottom Layer w0.3: v1(33.931,119.769) 33.971,119.729 34.518,119.729 35.599,118.647 v1(39.443,118.647)
PWM_Boost: R3.1 TP4.1 U13.3 | length 85
  Top Layer w0.3: v1(74.662,98.36) U13.3@74.662,99.706 ; v1(80.684,88.457) 80.705,88.478 80.705,90.799 v1(80.726,90.82)
  Bottom Layer w0.3: v1(74.662,98.36) 74.707,98.315 74.707,93.276 77.039,90.944 80.548,90.944 80.672,90.82 v1(80.726,90.82) ; v1(80.684,88.457) 80.313,88.086 80.313,66.12 86.432,60 97.141,60 100.838,56.303 102.613,54.528 ; TP4.1@104.166,56.191 104.166,56.08 102.613,54.528 ; R3.1@115.75,46.241 115.425,46.566 115.425,47.623 113.657,49.391 107.75,49.391 102.613,54.528
PWM_Boost_mcu: R120.2 R142.1 | length 61.8
  Top Layer w0.254: R120.2@33.646,115.475 v1(35.25,115.475) ; v1(38.341,99.456) 38.341,98.403 41.675,95.069 43.963,95.069 47.412,91.621 47.688,91.621 v1@47.698,91.61 ; v1@73.432,94.718 R142.1@73.432,96.131
  Top Layer w0.3: v1@47.698,91.61 v1(47.737,91.572) ; v1@73.392,94.678 v1(73.412,94.698) v1@73.432,94.718
  Inner Layer 2 w0.254: v1(38.341,99.456) 38.784,99.899 38.784,113.101 38.706,113.179 38.706,113.329 v1(38.658,113.377)
  Bottom Layer w0.254: v1(35.25,115.475) 36.56,115.475 v1(38.658,113.377) ; v1@47.754,91.555 70.269,91.555 v1(73.412,94.698)
  Bottom Layer w0.3: v1(47.737,91.572) v1@47.754,91.555
PWMiN_A_U_TIDA-011008_ACDC_Leg1: C115_U_TIDA-011008_ACDC_Leg1.2 R175_U_TIDA-011008_ACDC_Leg1.2 U16_U_TIDA-011008_ACDC_Leg1.9 | length 15.3
  Top Layer w0.3: v1(170.333,127.158) 170.344,127.147 171.51,127.147 C115_U_TIDA-011008_ACDC_Leg1.2@171.521,127.136
  Bottom Layer w0.3: U16_U_TIDA-011008_ACDC_Leg1.9@168.687,127.154 170.328,127.154 v1(170.333,127.158) 170.371,127.12 170.371,126.662 170.918,126.116 172.469,126.116 173.144,125.441 173.144,122.464 170.429,119.75 170.088,119.75 169.412,119.074 169.412,118.682 R175_U_TIDA-011008_ACDC_Leg1.2@169.267,118.537
PWMiN_A_U_TIDA-011008_ACDC_Leg2: C115_U_TIDA-011008_ACDC_Leg2.2 R175_U_TIDA-011008_ACDC_Leg2.2 U16_U_TIDA-011008_ACDC_Leg2.9 | length 15.8
  Top Layer w0.3: v1(116.2,115.158) C115_U_TIDA-011008_ACDC_Leg2.2@117.442,115.158
  Bottom Layer w0.3: U16_U_TIDA-011008_ACDC_Leg2.9@114.592,115.158 v1(116.2,115.158) 117.667,115.158 118.867,113.958 118.867,109.108 117.842,108.083 116.511,108.083 115.566,107.139 115.566,106.615 R175_U_TIDA-011008_ACDC_Leg2.2@115.323,106.371
PWMiN_B_U_TIDA-011008_ACDC_Leg1: C126_U_TIDA-011008_ACDC_Leg1.2 R180_U_TIDA-011008_ACDC_Leg1.2 U18_U_TIDA-011008_ACDC_Leg1.9 | length 4.1
  Bottom Layer w0.3: R180_U_TIDA-011008_ACDC_Leg1.2@146.264,126.913 147.923,126.913 148.163,127.154 U18_U_TIDA-011008_ACDC_Leg1.9@148.937,127.154 ; C126_U_TIDA-011008_ACDC_Leg1.2@147.901,125.527 U18_U_TIDA-011008_ACDC_Leg1.9@147.901,126.892
PWMiN_B_U_TIDA-011008_ACDC_Leg2: C126_U_TIDA-011008_ACDC_Leg2.2 R180_U_TIDA-011008_ACDC_Leg2.2 U18_U_TIDA-011008_ACDC_Leg2.9 | length 4.2
  Bottom Layer w0.3: R180_U_TIDA-011008_ACDC_Leg2.2@92.478,114.803 92.503,114.803 92.858,115.158 U18_U_TIDA-011008_ACDC_Leg2.9@94.175,115.158 ; C126_U_TIDA-011008_ACDC_Leg2.2@93.9,113.539 93.9,114.883 U18_U_TIDA-011008_ACDC_Leg2.9@94.175,115.158 ; U18_U_TIDA-011008_ACDC_Leg2.9@94.842,115.158 U18_U_TIDA-011008_ACDC_Leg2.9@94.175,115.158
PWMiN_Boost: C14.2 R3.2 U1.9 | length 3.6
  Bottom Layer w0.3: C14.2@115.785,43.35 115.785,44.606 R3.2@115.75,44.641 117.525,44.641 117.8,44.366 U1.9@117.8,44.25
Relay_Precharge: D2.2 K1.1 K3.1 Q1.3@46.398,143.989 | length 93.7
  Inner Layer 2 w0.6: v1(45.444,144.713) 47,146.269 47,157.75 53.5,164.25 85.75,164.25 91.382,169.882 K1.1@91.382,174.191 91.382,190.118 87.25,194.25 K3.1@82.75,194.25
Relay_Precharge_mcu: C33.1 R28.2 R146.2 U23.1 | length 106.4
  Top Layer w0.254: v1(6.25,111.277) 6.25,117.371 20.248,131.369 30.985,131.369 32.798,133.183 41.751,133.183 44.637,136.068 C33.1@45.477,136.068 46.656,136.068 47.246,135.478 47.246,135.425 47.819,134.852 51.094,134.852 51.791,135.548 51.791,136.867 51.215,137.443 U23.1@50.965,137.443 ; R146.2@27.71,99.073 27.731,99.052 v1(27.731,98.175)
  Inner Layer 2 w0.254: v1(6.202,96.717) 9.288,96.717 13.182,92.824 27.073,92.824 27.75,93.501 27.75,98.157 v1(27.731,98.175)
  Bottom Layer w0.254: v1(6.202,96.717) 6.202,96.786 5.999,96.99 5.999,110.957 6.25,111.208 v1(6.25,111.277)
Relay_Safe: D3.2 K2.1 K4.1 Q2.3@36.114,143.095 | length 81
  Inner Layer 2 w0.6: v1(35.25,143.714) 36.083,144.546 41.046,144.546 45.629,149.129 45.629,158.629 52.75,165.75 79.5,165.75 82.75,169 82.75,172 ; K2.1@79.93,174.191 82.121,172 82.75,172 ; K4.1@82.75,182.75 82.75,172
Relay_Safe_mcu: C40.1 R36.2 R149.2 U24.1 | length 61
  Top Layer w0.254: R149.2@12.79,108.49 8.062,108.49 5.605,110.947 5.605,117.416 20.095,131.906 30.75,131.906 34.04,135.196 C40.1@35.634,135.196 36.709,135.196 R36.2@36.951,134.954 36.951,134.929 37.921,133.959 41.03,133.959 41.732,134.661 41.732,135.93 41.583,136.079 41.274,136.079 U24.1@41.101,136.252
RESET: J19.4 J20.3 R164.2 U14.3 | length 50.6
  Top Layer w0.254: J19.4@211.32,6.145 212.566,6.145 215.657,9.236 218.952,9.236 219.25,8.938 219.25,8.175 219.468,7.957 219.468,5.094 219.25,4.875 219.25,4.475 J20.3@217,2.225 ; R164.2@249.69,8.49 249.709,8.471 249.709,7.143 v1(249.727,7.125)
  Bottom Layer w0.254: v1(219.25,4.822) 248.512,4.822 249.727,6.037 v1(249.727,7.125)
SCIA_RX: R147.2 U22.2 | length 36
  Top Layer w0.254: R147.2@33.664,103.374 33.689,103.374 35.051,102.012 v1(35.051,91.555)
  Inner Layer 2 w0.254: v1(35.051,86.57) v1(35.051,91.555)
  Bottom Layer w0.3: U22.2@28.93,71.065 29.011,71.146 29.893,71.146 30.299,71.552 30.299,79.846 35.051,84.598 v1(35.051,86.57)
SCIA_TX: R152.2 U22.3 | length 34.1
  Top Layer w0.254: v1@33.645,86.551 v1(33.664,86.57) ; R152.2@33.664,101.856 v1(33.664,91.636) v1@33.69,91.61
  Inner Layer 2 w0.254: v1(33.664,86.57) v1(33.664,91.636)
  Bottom Layer w0.3: U22.3@28.93,72.335 27.5,72.335 26.895,72.941 26.895,77.266 33.664,84.035 v1(33.664,86.57)
SCIB_RX: R187.2 U6.2 | length 82.5
  Top Layer w0.254: v1(11.4,125.654) 9.724,125.654 3.202,119.133 3.202,96.224 5.974,93.453 5.974,91.192 6.904,90.262 13.204,90.262 14.754,88.712 14.754,88.15 15.595,87.308 17.041,87.308 21.695,82.654 21.695,80.324 v1(21.217,79.846) ; v1(23.347,122.106) 24.924,122.106 25.56,121.471 R187.2@25.56,120.204
  Inner Layer 2 w0.254: v1(11.4,125.654) 11.818,125.654 14.199,123.273 v1(16.911,123.273)
  Bottom Layer w0.254: v1(16.911,123.273) 18.078,122.106 v1(23.347,122.106) ; U6.2@18.46,79.885 18.48,79.865 21.198,79.865 v1(21.217,79.846)
SCIB_TX: R184.2 U6.3 | length 84.6
  Top Layer w0.254: v1(12.793,127.25) 10.338,127.25 2.753,119.664 2.753,95.968 3.38,95.34 3.38,90.699 4.292,89.786 12.917,89.786 14.143,88.561 14.143,88.177 17.024,85.295 17.024,79.215 17.042,79.196 17.042,79.017 v1(17.091,78.968) ; v1(24.073,122.917) 25.64,122.917 26.692,121.865 26.692,120.225 R184.2@27.04,119.877
  Inner Layer 2 w0.254: v1(12.793,127.25) 14.129,127.25 v1(17.402,123.977)
  Bottom Layer w0.254: v1(17.091,78.968) 17.16,78.968 17.386,78.742 18.334,78.742 U6.3@18.46,78.615 ; v1@17.41,123.977 18.47,122.917 v1(24.073,122.917)
SN1: J7.1 TP29_U_TIDA-011008_ACDC_Leg1.1 U16_U_TIDA-011008_ACDC_Leg1.13 U16_U_TIDA-011008_ACDC_Leg1.14 U16_U_TIDA-011008_ACDC_Leg1.15 U16_U_TIDA-011008_ACDC_Leg1.16 U17_U_TIDA-011008_ACDC_Leg1.5 U17_U_TIDA-011008_ACDC_Leg1.6 U17_U_TIDA-011008_ACDC_Leg1.7 U18_U_TIDA-011008_ACDC_Leg1.1 U18_U_TIDA-011008_ACDC_Leg1.2 U18_U_TIDA-011008_ACDC_Leg1.3 U18_U_TIDA-011008_ACDC_Leg1.4 U18_U_TIDA-011008_ACDC_Leg1.5 U18_U_TIDA-011008_ACDC_Leg1.6 U18_U_TIDA-011008_ACDC_Leg1.7 U18_U_TIDA-011008_ACDC_Leg1.8
  other v1: 164.354,127.12 160.544,127.826 164.354,128.235 160.544,128.97 164.354,129.304 160.544,130.117 164.354,130.448
SN2: J9.1 TP29_U_TIDA-011008_ACDC_Leg2.1 U16_U_TIDA-011008_ACDC_Leg2.13 U16_U_TIDA-011008_ACDC_Leg2.14 U16_U_TIDA-011008_ACDC_Leg2.15 U16_U_TIDA-011008_ACDC_Leg2.16 U17_U_TIDA-011008_ACDC_Leg2.5 U17_U_TIDA-011008_ACDC_Leg2.6 U17_U_TIDA-011008_ACDC_Leg2.7 U18_U_TIDA-011008_ACDC_Leg2.1 U18_U_TIDA-011008_ACDC_Leg2.2 U18_U_TIDA-011008_ACDC_Leg2.3 U18_U_TIDA-011008_ACDC_Leg2.4 U18_U_TIDA-011008_ACDC_Leg2.5 U18_U_TIDA-011008_ACDC_Leg2.6 U18_U_TIDA-011008_ACDC_Leg2.7 U18_U_TIDA-011008_ACDC_Leg2.8
  other v1: 106.308,115.026 110.206,115.07 106.308,116.224 110.206,116.268 106.306,117.389 110.204,117.433 106.306,118.732 110.204,118.776
SN_U_TIDA-011008_ACDC_Leg1: C19_U_TIDA-011008_ACDC_Leg1.2 C109_U_TIDA-011008_ACDC_Leg1.1 C110_U_TIDA-011008_ACDC_Leg1.2 C111_U_TIDA-011008_ACDC_Leg1.2 C112_U_TIDA-011008_ACDC_Leg1.2 C113_U_TIDA-011008_ACDC_Leg1.1 C114_U_TIDA-011008_ACDC_Leg1.1 C115_U_TIDA-011008_ACDC_Leg1.1 C117_U_TIDA-011008_ACDC_Leg1.1 D14_U_TIDA-011008_ACDC_Leg1.2 R177_U_TIDA-011008_ACDC_Leg1.1 TP28_U_TIDA-011008_ACDC_Leg1.1 U15_U_TIDA-011008_ACDC_Leg1.5 U16_U_TIDA-011008_ACDC_Leg1.10 U21_U_TIDA-011008_ACDC_Leg1.3 | length 8.6
  Top Layer w0.6: U15_U_TIDA-011008_ACDC_Leg1.5@171.992,114.804 171.992,114.719 v1(172.53,114.719) ; v1(172.707,127.859) 172.719,127.871 172.719,128.492 C113_U_TIDA-011008_ACDC_Leg1.1@172.744,128.517 172.744,128.542 C113_U_TIDA-011008_ACDC_Leg1.1@172.769,128.567 ; C115_U_TIDA-011008_ACDC_Leg1.1@172.721,127.136 v1@172.721,127.859 ; R177_U_TIDA-011008_ACDC_Leg1.1@173.296,130.388 173.471,130.213 173.881,130.213 v1(174.046,130.048)
  Top Layer w0.8: C110_U_TIDA-011008_ACDC_Leg1.2@170.4,122.25 170.444,122.206 v1(170.444,120.875) 170.444,119.544 C111_U_TIDA-011008_ACDC_Leg1.2@170.489,119.5
  Bottom Layer w0.3: C114_U_TIDA-011008_ACDC_Leg1.1@173.144,116.992 173.144,117.067 C114_U_TIDA-011008_ACDC_Leg1.1@173.369,117.292
  Bottom Layer w0.6: U16_U_TIDA-011008_ACDC_Leg1.10@168.687,128.354 168.741,128.3 v1(170.215,128.3)
  Bottom Layer w0.8: D14_U_TIDA-011008_ACDC_Leg1.2@170.575,122.404 170.575,122.387 170.632,122.329 170.77,122.329 v1(171.271,121.829)
  other v1: 166.755,124.623 170.017,126.093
